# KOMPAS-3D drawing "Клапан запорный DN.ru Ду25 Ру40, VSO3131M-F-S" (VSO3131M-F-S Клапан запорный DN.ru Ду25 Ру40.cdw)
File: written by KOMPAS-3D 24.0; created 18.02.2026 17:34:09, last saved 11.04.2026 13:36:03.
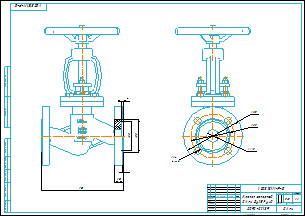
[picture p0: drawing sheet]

Document properties: Автор: R2D2; Форматы листов документа: A2; Полное имя файла: VSO3131M-F-S Клапан запорный DN.ru Ду25 Ру40.m3d; Масса: 5.85; Наименование: Клапан запорный DN.ru Ду25 Ру40; Количество листов документа: 1; Примечание: D090-02139

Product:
- Part/product: Клапан запорный DN.ru Ду25 Ру40  | designation VSO3131M-F-S
    Масса: 5.85
    Раздел спецификации: Прочие изделия
    Примечание: D090-02139

Views: Проекционный вид 2
Referenced files in E:\Работа\Зайцев\VSO3131M-F-S Клапан запорный DN.ru Ду15-100 Ру40\DN25\: VSO3131M-F-S Клапан запорный DN.ru Ду25 Ру40.m3d
Referenced files in E:\Работа\Зайцев\Для компаса\: чертеж DN.ru А3.cdt
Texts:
  VSO3131M-F-S
  чертеж DN.ru А3.cdt
  Клапан запорный
  DN.ru Ду25 Ру40
  Клапан запорный DN.ru Ду25 Ру40
  VSO3131M-F-S Клапан запорный DN.ru Ду25 Ру40
Dimensions and other numbers on the sheet: 0; 3; 4; 115; 85; 25; 14; 4 отв.; 1; 1:1; 2; 5,85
